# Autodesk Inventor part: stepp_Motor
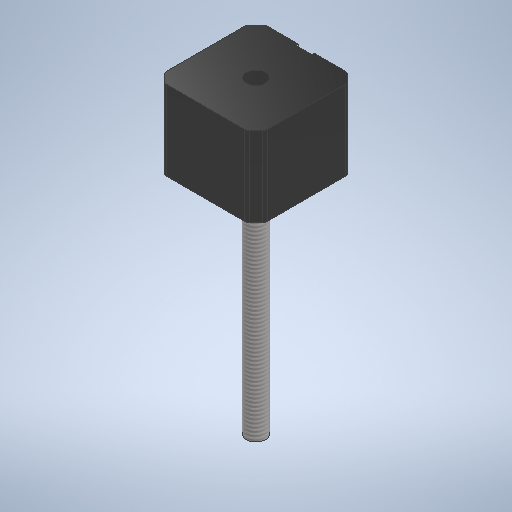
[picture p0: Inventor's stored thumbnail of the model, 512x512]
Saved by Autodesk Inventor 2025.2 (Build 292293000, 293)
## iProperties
Created: 2025-04
Part Number: stepp_Motor
Material: Generic
Document SubType Name: Modeling
Designer: Jarni
Density: 1 g/cm^3
Appearance: Default
Author: Jarni
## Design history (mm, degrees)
sketch "Sketch1"
  geometry: C1 r 4 at (0, 0); 1 further point
  constraints: 1 centre point, 1 coincident
  dimensions: "d0" = 8 diameter of C1
extrude "Extrusion1" new body sketch "Sketch1" distance "d1" = 95; taper "d2" = 0 deg
thread "Thread1" dims "d3" = 310, "d4" = 0
sketch "Sketch2"
  geometry: L1 (20.9, -20.9)-(-20.9, -20.9); L2 (-20.9, -20.9)-(-20.9, 20.9); L3 (-20.9, 20.9)-(20.9, 20.9); L4 (20.9, 20.9)-(20.9, -20.9); L5 (20.9, -20.9)-(-20.9, 20.9); L6 (-20.9, -20.9)-(20.9, 20.9); C1 r 4 at (0, 0) reference; 1 further point
  constraints: 12 end point, 2 midpoint, 2 parallel, 1 horizontal, 1 perpendicular
  dimensions: "d5" = 41.8 distance of L1.end L2.end; "d6" = 41.8 distance of L2.end L3.end
extrude "Extrusion2" join sketch "Sketch2" distance "d7" = 33; taper "d8" = 0 deg
sketch "Sketch3"
  geometry: L1 (-15.5, 15.5)-(15.5, 15.5); L2 (15.5, 15.5)-(15.5, -15.5); L3 (15.5, -15.5)-(-15.5, -15.5); L4 (-15.5, -15.5)-(-15.5, 15.5); L5 (-15.5, 15.5)-(15.5, -15.5); L6 (15.5, 15.5)-(-15.5, -15.5); C1 r 1.5 at (15.5, 15.5); C2 r 1.5 at (15.5, -15.5); C3 r 1.5 at (-15.5, -15.5); C4 r 1.5 at (-15.5, 15.5); 1 further point
  constraints: 12 end point, 4 centre point, 4 coincident, 2 midpoint, 2 parallel, 1 horizontal, 1 perpendicular
  dimensions: "d9" = 31 distance of L2.end L3.end; "d10" = 31 distance of L1.end L2.end; "d11" = 3 diameter of C1; "d12" = 3 diameter of C2; "d13" = 3 diameter of C3; "d14" = 3 diameter of C4
extrude "Extrusion3" cut sketch "Sketch3" distance "d15" = 5; taper "d16" = 0 deg
sketch "Sketch4"
  geometry: L1 (-20.9, 20.9)-(20.9, 20.9) reference; L2 (-20.9, -20.9)-(-20.9, 20.9) reference; L3 (20.9, -20.9)-(-20.9, -20.9) reference; L4 (20.9, 20.9)-(20.9, -20.9) reference; L5 (-20.9, 20.9)-(20.9, 20.9) reference; L6 (-20.9, -20.9)-(-20.9, 20.9) reference; L7 (20.9, 20.9)-(20.9, -20.9) reference; L8 (20.9, -17)-(17, -20.9); L9 (20.9, -20.9)-(-20.9, -20.9) reference; L10 (-17, -20.9)-(-20.9, -17); L11 (-17, 20.9)-(-20.9, 17); L12 (17, 20.9)-(20.9, 17); C1 r 1.5 at (-15.5, -15.5) reference; C2 r 1.5 at (15.5, -15.5) reference; C3 r 1.5 at (-15.5, 15.5) reference; C4 r 1.5 at (15.5, 15.5) reference; C5 r 4 at (0, 0) reference; 10 further points
  constraints: 8 end point, 8 point on line
  dimensions: "d17" = 34 distance of L8.start L12.end; "d18" = 34 distance of L10.start L8.end; "d19" = 34 distance of L11.end L10.end; "d20" = 34 distance of L12.start L11.start; "d21" = 3.9 distance of L3.start L8.start; "d22" = 3.9 distance of L8.end L3.start; "d23" = 3.9 distance of L1.end L12.start; "d24" = 3.9 distance of L1.start L11.end
extrude "Extrusion4" cut sketch "Sketch4" distance "d25" = 40; taper "d26" = 0 deg
fillet "Fillet1" dims "d27" = 2
sketch "Sketch5"
  geometry: C1 r 11 at (0, 0); 1 further point
  constraints: 1 centre point, 1 coincident
  dimensions: "d28" = 22 diameter of C1
extrude "Extrusion5" join sketch "Sketch5" distance "d29" = 2; taper "d30" = 0 deg
sketch "Sketch6"
  geometry: L1 (32.343, 33)-(0, 33) reference; L2 (12.923, 33)-(19.443, 33); L3 (19.443, 33)-(19.443, 26.48); L4 (19.443, 26.48)-(12.923, 26.48); L5 (12.923, 26.48)-(12.923, 33); L6 (32.343, 33)-(32.343, 0) reference; 2 further points
  constraints: 8 end point, 2 parallel, 1 horizontal, 1 perpendicular, 1 point on line
  dimensions: "d31" = 6.52 distance of L3.end L4.end; "d32" = 6.52 distance of L2.end L3.end; "d33" = 12.9 distance between parallel lines of L6 L3
extrude "Extrusion6" cut sketch "Sketch6" distance "d34" = 1; taper "d35" = 0 deg
body "Solid1"
node "Projected Loop1"
